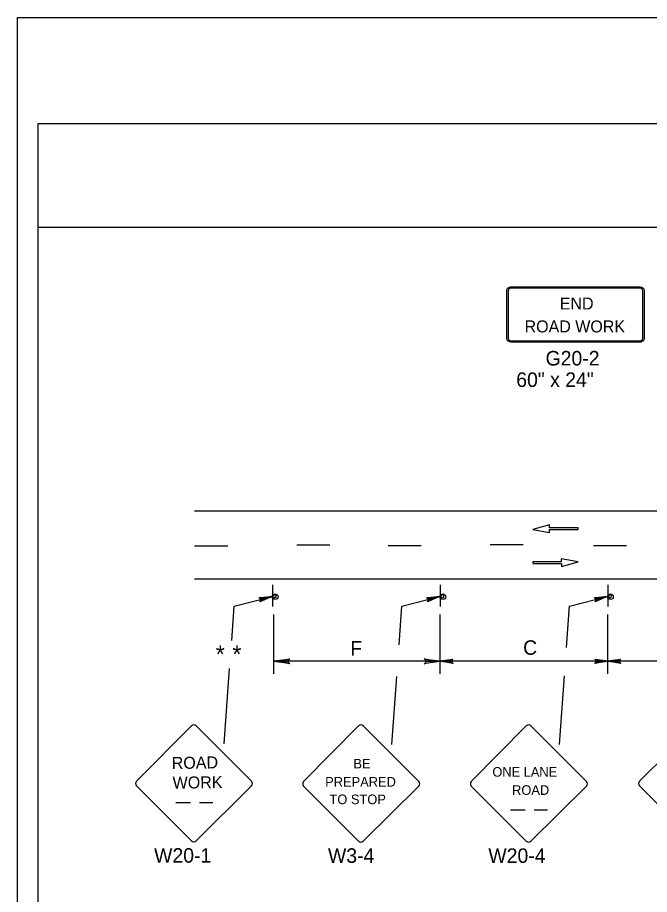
# Model space of a CAD drawing. Extents: x -14145 to -13521, y 30244 to 30661.
# Drawn here: x -13892.17 to -13883.04, y 30356.64 to 30369.31 of the extents above; entities that cross this region are included whole.
import ezdxf

# ---------------------------------------------------------------- set-up
doc = ezdxf.new("R2010")
doc.units = 0
for name, color, linetype in [('1', 7, 'Continuous'), ('10', 7, 'Continuous'), ('2', 7, 'Continuous'), ('61', 7, 'Continuous')]:
    doc.layers.add(name, color=color, linetype=linetype)

msp = doc.modelspace()

# ---------------------------------------------------------------- linework, layer by layer
at = {"layer": '1'}
for p, q in [((-13883.17, 30365.413), (-13885.043, 30365.413)), ((-13883.17, 30365.413), (-13885.043, 30365.413)), ((-13883.17, 30365.398), (-13885.043, 30365.398)), ((-13883.17, 30365.398), (-13885.043, 30365.398)), ((-13885.104, 30365.362), (-13885.104, 30364.674)), ((-13885.079, 30365.362), (-13885.079, 30364.674)), ((-13883.134, 30364.674), (-13883.134, 30365.362)), ((-13883.109, 30364.674), (-13883.109, 30365.362)), ((-13885.043, 30364.637), (-13883.17, 30364.637)), ((-13885.043, 30364.622), (-13883.17, 30364.622)), ((-13889.613, 30362.181), (-13863.333, 30362.181)), ((-13884.483, 30361.979), (-13884.725, 30361.913)), ((-13884.483, 30361.934), (-13884.483, 30361.979)), ((-13884.725, 30361.913), (-13884.481, 30361.867)), ((-13884.067, 30361.934), (-13884.483, 30361.934)), ((-13884.481, 30361.867), (-13884.481, 30361.912)), ((-13884.481, 30361.912), (-13884.067, 30361.912)), ((-13884.067, 30361.912), (-13884.067, 30361.934)), ((-13889.133, 30361.671), (-13889.613, 30361.671)), ((-13887.657, 30361.683), (-13888.137, 30361.683)), ((-13886.337, 30361.677), (-13886.817, 30361.677)), ((-13884.861, 30361.689), (-13885.341, 30361.689)), ((-13883.367, 30361.677), (-13883.847, 30361.677)), ((-13884.311, 30361.443), (-13884.725, 30361.443)), ((-13884.725, 30361.443), (-13884.725, 30361.421)), ((-13884.067, 30361.442), (-13884.311, 30361.489)), ((-13884.311, 30361.489), (-13884.311, 30361.443)), ((-13884.308, 30361.376), (-13884.067, 30361.442)), ((-13884.725, 30361.421), (-13884.308, 30361.421)), ((-13884.308, 30361.421), (-13884.308, 30361.376)), ((-13889.613, 30361.197), (-13863.333, 30361.197)), ((-13888.488, 30361.112), (-13888.488, 30360.8)), ((-13886.064, 30361.112), (-13886.064, 30360.8)), ((-13883.64, 30361.112), (-13883.64, 30360.8)), ((-13889.041, 30360.805), (-13888.494, 30360.945)), ((-13886.617, 30360.805), (-13886.07, 30360.945)), ((-13884.193, 30360.805), (-13883.646, 30360.945)), ((-13889.077, 30360.308), (-13889.041, 30360.805)), ((-13888.466, 30359.827), (-13888.466, 30360.683)), ((-13886.657, 30360.245), (-13886.616, 30360.805)), ((-13886.064, 30359.827), (-13886.064, 30360.683)), ((-13884.236, 30360.206), (-13884.192, 30360.806)), ((-13883.64, 30359.827), (-13883.64, 30360.683)), ((-13886.064, 30360.007), (-13888.466, 30360.007)), ((-13883.64, 30360.007), (-13886.064, 30360.007)), ((-13881.216, 30360.007), (-13883.64, 30360.007)), ((-13889.187, 30358.816), (-13889.107, 30359.905)), ((-13884.339, 30358.806), (-13884.266, 30359.796)), ((-13886.763, 30358.806), (-13886.691, 30359.785)), ((-13889.659, 30359.076), (-13890.454, 30358.273)), ((-13888.79, 30358.273), (-13889.593, 30359.076)), ((-13887.242, 30359.072), (-13888.037, 30358.269)), ((-13886.373, 30358.269), (-13887.176, 30359.072)), ((-13884.818, 30359.072), (-13885.613, 30358.269)), ((-13883.949, 30358.269), (-13884.752, 30359.072)), ((-13882.378, 30359.07), (-13883.181, 30358.275)), ((-13890.454, 30358.207), (-13889.659, 30357.412)), ((-13889.593, 30357.412), (-13888.79, 30358.207)), ((-13888.037, 30358.203), (-13887.242, 30357.408)), ((-13887.176, 30357.408), (-13886.373, 30358.203)), ((-13885.613, 30358.203), (-13884.818, 30357.408)), ((-13884.752, 30357.408), (-13883.949, 30358.203)), ((-13883.181, 30358.207), (-13882.378, 30357.405)), ((-13889.886, 30357.965), (-13889.675, 30357.965)), ((-13889.543, 30357.965), (-13889.35, 30357.965)), ((-13885.045, 30357.861), (-13884.834, 30357.861)), ((-13884.702, 30357.861), (-13884.509, 30357.861))]:
    msp.add_line(p, q, dxfattribs=at)
for points in [[(-13888.674, 30360.921), (-13888.662, 30360.909), (-13888.494, 30360.945), (-13888.674, 30360.921), (-13888.68, 30360.927), (-13888.494, 30360.945), (-13888.656, 30360.891), (-13888.662, 30360.879), (-13888.494, 30360.945), (-13888.668, 30360.867), (-13888.662, 30360.879)], [(-13886.25, 30360.921), (-13886.238, 30360.909), (-13886.07, 30360.945), (-13886.25, 30360.921), (-13886.256, 30360.927), (-13886.07, 30360.945), (-13886.232, 30360.891), (-13886.238, 30360.879), (-13886.07, 30360.945), (-13886.244, 30360.867), (-13886.238, 30360.879)], [(-13883.826, 30360.921), (-13883.814, 30360.909), (-13883.646, 30360.945), (-13883.826, 30360.921), (-13883.832, 30360.927), (-13883.646, 30360.945), (-13883.808, 30360.891), (-13883.814, 30360.879), (-13883.646, 30360.945), (-13883.82, 30360.867), (-13883.814, 30360.879)], [(-13888.248, 30359.98), (-13888.256, 30359.995), (-13888.466, 30360.007), (-13888.248, 30359.98), (-13888.237, 30359.97), (-13888.466, 30360.007), (-13888.256, 30360.017), (-13888.248, 30360.033), (-13888.466, 30360.007), (-13888.237, 30360.043), (-13888.248, 30360.033)], [(-13886.282, 30360.034), (-13886.274, 30360.019), (-13886.064, 30360.007), (-13886.282, 30360.034), (-13886.293, 30360.044), (-13886.064, 30360.007), (-13886.274, 30359.997), (-13886.281, 30359.981), (-13886.064, 30360.007), (-13886.293, 30359.971), (-13886.281, 30359.981)], [(-13885.884, 30359.989), (-13885.89, 30360.001), (-13886.064, 30360.007), (-13885.884, 30359.989), (-13885.878, 30359.977), (-13886.064, 30360.007), (-13885.89, 30360.019), (-13885.884, 30360.031), (-13886.064, 30360.007), (-13885.878, 30360.037), (-13885.884, 30360.031)], [(-13883.82, 30360.031), (-13883.808, 30360.013), (-13883.64, 30360.007), (-13883.82, 30360.031), (-13883.826, 30360.037), (-13883.64, 30360.007), (-13883.808, 30359.995), (-13883.82, 30359.983), (-13883.64, 30360.007), (-13883.826, 30359.977), (-13883.82, 30359.983)], [(-13883.46, 30359.989), (-13883.466, 30360.001), (-13883.64, 30360.007), (-13883.46, 30359.989), (-13883.454, 30359.977), (-13883.64, 30360.007), (-13883.466, 30360.019), (-13883.46, 30360.031), (-13883.64, 30360.007), (-13883.454, 30360.037), (-13883.46, 30360.031)]]:
    msp.add_lwpolyline(points, dxfattribs=at)
for centre in [(-13888.448, 30360.94), (-13886.024, 30360.94), (-13883.6, 30360.94)]:
    msp.add_circle(centre, 0.0408, dxfattribs=at)
for centre, radius, start, end in [((-13888.453, 30360.948), 0.0214, 189.521, 184.2501), ((-13886.029, 30360.948), 0.0214, 189.521, 184.2501), ((-13883.605, 30360.948), 0.0214, 189.521, 184.2501), ((-13889.625, 30359.043), 0.0465, 45, 135), ((-13887.208, 30359.04), 0.0465, 45, 135), ((-13884.784, 30359.04), 0.0465, 45, 135), ((-13890.42, 30358.24), 0.0465, 135, 225), ((-13888.822, 30358.24), 0.0465, 315, 45), ((-13888.003, 30358.237), 0.0465, 135, 225), ((-13886.405, 30358.237), 0.0465, 315, 45), ((-13885.579, 30358.237), 0.0465, 135, 225), ((-13883.981, 30358.237), 0.0465, 315, 45), ((-13883.148, 30358.241), 0.0465, 135, 225), ((-13889.625, 30357.445), 0.0465, 225, 315), ((-13887.208, 30357.442), 0.0465, 225, 315), ((-13884.784, 30357.442), 0.0465, 225, 315)]:
    msp.add_arc(centre, radius, start, end, dxfattribs=at)
for centre, major_axis, ratio, start_param, end_param in [((-13885.042, 30365.361), (0.0609, 0), 0.839899, 1.570796, 3.141593), ((-13885.042, 30365.361), (0, -0.0365), 0.999938, 3.141593, 4.712389), ((-13883.169, 30365.361), (-0.0609, 0), 0.839899, 3.141593, 4.712389), ((-13883.169, 30365.361), (0, 0.0365), 0.999938, 4.712389, 6.283185), ((-13885.042, 30364.673), (0.0609, 0), 0.839899, 3.141593, 4.712389), ((-13885.042, 30364.673), (0, -0.0365), 0.999938, 4.712389, 6.283185), ((-13883.169, 30364.673), (0, 0.0365), 0.999938, 3.141593, 4.712389), ((-13883.169, 30364.673), (-0.0609, 0), 0.839899, 1.570796, 3.141593)]:
    msp.add_ellipse(centre, major_axis=major_axis, ratio=ratio, start_param=start_param, end_param=end_param, dxfattribs=at)
at = {"layer": '10'}
for p, q in [((-13891.874, 30367.777), (-13860.422, 30367.777)), ((-13891.874, 30345.207), (-13891.874, 30367.777)), ((-13891.874, 30366.277), (-13860.422, 30366.277))]:
    msp.add_line(p, q, dxfattribs=at)
at = {"layer": '61'}
msp.add_lwpolyline([(-13892.174, 30369.307), (-13859.174, 30369.307), (-13859.174, 30343.807), (-13892.174, 30343.807)], close=True, dxfattribs=at)

# ---------------------------------------------------------------- texts
at = {"layer": '1'}
for s, height, p in [('END', 0.173, (-13884.333, 30365.089)), ('ROAD WORK', 0.173, (-13884.842, 30364.758)), ('BE', 0.1386, (-13887.317, 30358.459)), ('ONE LANE', 0.1386, (-13885.308, 30358.34)), ('PREPARED', 0.1389, (-13887.725, 30358.196)), ('ROAD', 0.1389, (-13885.023, 30358.077)), ('TO STOP', 0.139, (-13887.663, 30357.943))]:
    msp.add_text(s, height=height, dxfattribs=at).set_placement(p)
for s, height, rotation, p in [('ROAD', 0.1735, 0.7566, (-13889.943, 30358.451)), ('WORK', 0.1733, 0.7588, (-13889.93, 30358.166))]:
    msp.add_text(s, height=height, rotation=rotation, dxfattribs=at).set_placement(p)
at = {"layer": '2'}
for s, height, p in [('G20-2', 0.21, (-13884.539, 30364.28)), ('60" x 24"', 0.21, (-13884.963, 30363.97)), ('C', 0.21, (-13884.863, 30360.1)), ('*', 0.252, (-13889.308, 30359.984)), ('*', 0.252, (-13889.067, 30359.984)), ('F', 0.21, (-13887.362, 30360.09)), ('W20-1', 0.21, (-13890.199, 30357.097)), ('W3-4', 0.21, (-13887.685, 30357.095)), ('W20-4', 0.21, (-13885.366, 30357.094))]:
    msp.add_text(s, height=height, dxfattribs=at).set_placement(p)

doc.saveas('drawing.dxf')
